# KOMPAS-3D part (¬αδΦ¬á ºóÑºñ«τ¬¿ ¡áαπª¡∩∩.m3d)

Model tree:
1. Эскиз:1
2. Операция выдавливания:1
     Расстояние 1 = 1; Расстояние 2 = 11
3. Эскиз:2
4. Операция выдавливания:2
     Расстояние 1 = 1; Расстояние 2 = 1
5. Массив по концентрической сетке:1  (with: Операция выдавливания:2)  (labels: Экземпляр ( 1, 1 ); Экземпляр ( 1, 2 ); Экземпляр ( 1, 3 ); Экземпляр ( 1, 4 ))
     N 2 = 6; Шаг 2 = 360; Номер 2 = 1
6. Эскиз:3
7. Операция выдавливания:3
     Расстояние 1 = 1; Расстояние 2 = 1
8. Эскиз:4
9. Вырезать элемент выдавливания:1
     Расстояние 1 = 1
10. Эскиз:5
11. Операция выдавливания:4
     Расстояние 1 = 1; Расстояние 2 = 1
12. Скругление:1
     Радиус = 0.2
13. Скругление:2
     Радиус = 0.5
14. Скругление:3
     Радиус = 0.2
15. Эскиз:6
16. Операция выдавливания:5
     Расстояние 1 = 0.5; Расстояние 2 = 1
17. Массив по концентрической сетке:2  (with: Операция выдавливания:5)  (labels: Экземпляр ( 1, 1 ); Экземпляр ( 1, 2 ); Экземпляр ( 1, 3 ); Экземпляр ( 1, 4 ))
     N 2 = 6; Шаг 2 = 360; Номер 2 = 1
18. Эскиз:7
19. Вырезать элемент выдавливания:2
     Расстояние 1 = 0.1
20. Эскиз:8
21. Операция выдавливания:6
     Расстояние 1 = 0.1; Расстояние 2 = 1
22. Массив по концентрической сетке:3  (with: Вырезать элемент выдавливания:2, Операция выдавливания:6)  (labels: Экземпляр ( 1, 1 ); Экземпляр ( 1, 2 ); Экземпляр ( 1, 3 ); Экземпляр ( 1, 4 ))
     N 2 = 80; Шаг 2 = 360; Номер 2 = 1
23. Скругление:6
     Радиус = 0.1

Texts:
  крышка звездочки наружняя
  stalker61
  Сплав АЛ8  ГОСТ 1583-93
